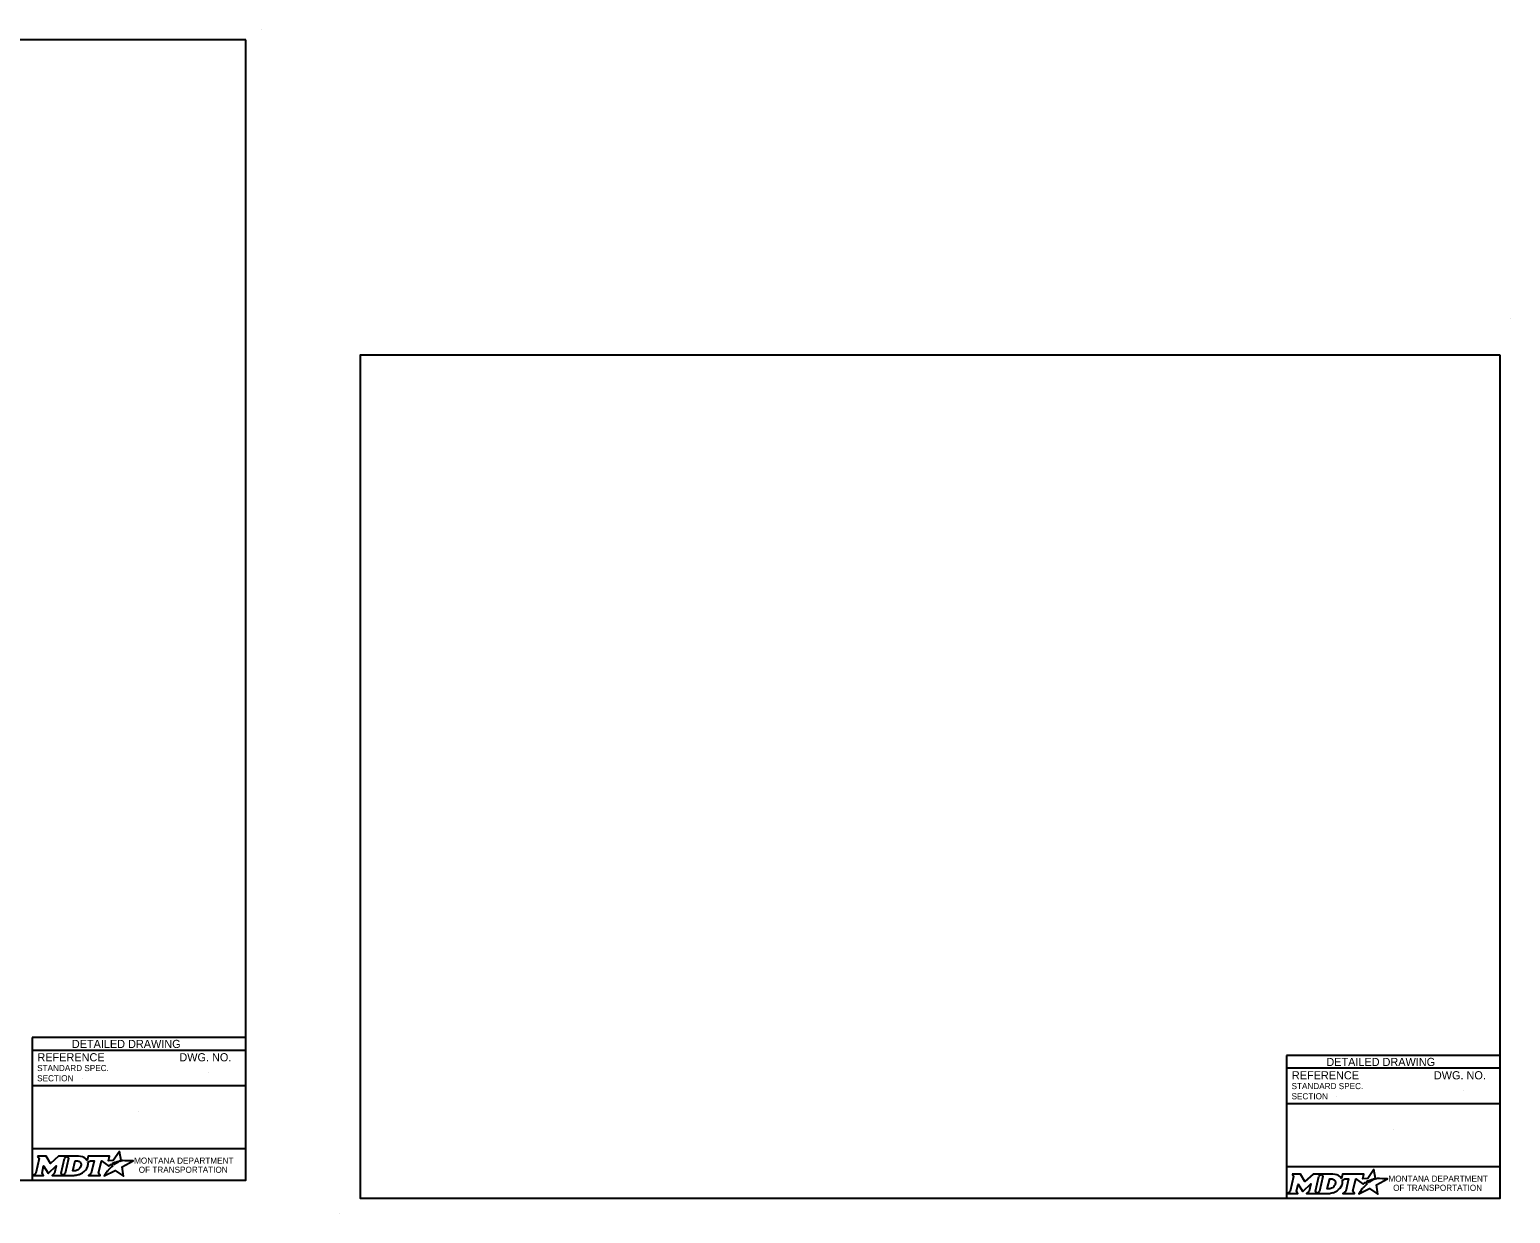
# Model space of a CAD drawing. Extents: x 49991.4 to 50021, y 49987.6 to 50011.4.
# Drawn here: x 50006.49 to 50021.04, y 49999.74 to 50011.36 of the extents above; entities that cross this region are included whole.
import ezdxf

# ---------------------------------------------------------------- set-up
doc = ezdxf.new("R2010")
doc.units = 0
for name, color, linetype in [('Default', 7, 'Continuous'), ('Level 1', 7, 'Continuous'), ('Level 2', 7, 'Continuous'), ('Level 4', 7, 'Continuous')]:
    doc.layers.add(name, color=color, linetype=linetype)

msp = doc.modelspace()

# ---------------------------------------------------------------- linework, layer by layer
at = {"layer": 'Default'}
for points in [[(50018.893, 50000.121), (50018.907, 50000.097), (50018.874, 49999.954), (50018.848, 49999.931), (50018.95, 49999.931), (50018.936, 49999.954), (50018.952, 50000.024), (50018.996, 49999.955), (50019.002, 49999.955), (50019.077, 50000.025), (50019.06, 49999.954), (50019.035, 49999.932), (50019.137, 49999.932), (50019.123, 49999.955), (50019.156, 50000.097)], [(50019.156, 50000.097), (50019.182, 50000.121), (50019.099, 50000.121), (50019.02, 50000.048), (50018.975, 50000.12), (50018.893, 50000.121)], [(50019.295, 50000.121), (50019.182, 50000.121), (50019.196, 50000.098), (50019.163, 49999.954), (50019.137, 49999.932), (50019.248, 49999.932)], [(50019.7, 50000.068), (50019.69, 50000.074), (50019.702, 50000.076), (50019.713, 50000.078), (50019.696, 50000.168), (50019.636, 50000.077), (50019.589, 50000.076), (50019.599, 50000.12), (50019.39, 50000.121), (50019.38, 50000.078), (50019.374, 50000.086)], [(50019.319, 50000.034), (50019.318, 50000.026), (50019.315, 50000.017), (50019.311, 50000.008), (50019.305, 50000.001), (50019.299, 49999.994), (50019.291, 49999.988), (50019.282, 49999.983), (50019.273, 49999.979), (50019.264, 49999.977), (50019.255, 49999.976), (50019.239, 49999.976), (50019.263, 50000.076), (50019.279, 50000.076), (50019.286, 50000.075), (50019.294, 50000.073), (50019.301, 50000.07), (50019.307, 50000.066), (50019.311, 50000.061), (50019.315, 50000.055), (50019.318, 50000.049), (50019.319, 50000.042), (50019.32, 50000.038), (50019.319, 50000.034)], [(50019.293, 49999.939), (50019.302, 49999.942), (50019.315, 49999.947), (50019.335, 49999.958)], [(50019.387, 50000.062), (50019.411, 50000.075), (50019.448, 50000.075), (50019.42, 49999.954), (50019.392, 49999.931), (50019.508, 49999.931), (50019.491, 49999.954), (50019.52, 50000.075), (50019.591, 50000.023), (50019.612, 50000.038), (50019.632, 50000.027)], [(50019.576, 49999.971), (50019.561, 49999.947), (50019.556, 49999.939), (50019.55, 49999.931), (50019.548, 49999.926), (50019.653, 49999.979), (50019.737, 49999.924), (50019.724, 50000.017), (50019.831, 50000.075), (50019.782, 50000.076), (50019.751, 50000.077), (50019.731, 50000.077), (50019.724, 50000.075), (50019.719, 50000.074), (50019.711, 50000.072), (50019.7, 50000.068)], [(50019.59, 49999.987), (50019.59, 49999.987)], [(50019.65, 50000.04), (50019.648, 50000.039), (50019.629, 50000.048), (50019.639, 50000.054), (50019.644, 50000.056), (50019.652, 50000.06), (50019.658, 50000.063), (50019.666, 50000.066), (50019.673, 50000.068), (50019.685, 50000.061), (50019.681, 50000.059), (50019.676, 50000.056), (50019.672, 50000.054), (50019.667, 50000.051), (50019.665, 50000.05), (50019.662, 50000.049), (50019.66, 50000.047), (50019.658, 50000.046), (50019.655, 50000.044), (50019.652, 50000.042), (50019.65, 50000.04)]]:
    msp.add_lwpolyline(points, dxfattribs=at)
for centre, radius, start, end in [((50019.274, 50000.059), 0.118, 300.9103, 339.1383), ((50019.319, 50000.042), 0.0709, 339.5329, 15.8582)]:
    msp.add_arc(centre, radius, start, end, dxfattribs=at)
for centre, major_axis, ratio, start_param, end_param in [((50019.293, 50000.073), (0.0834, -0.0037), 0.568097, 0.61298, 1.570796), ((50019.349, 50000.081), (0.0361, -0.0295), 0.469099, 1.225588, 1.570796), ((50019.583, 49999.979), (-0.00694, -0.00806), 0.008222, 0, 3.137361), ((50019.6, 49999.997), (-0.0098, -0.0102), 0.016458, 3.141593, 6.279097), ((50019.621, 50000.017), (-0.0112, -0.0097), 0.021651, 3.157348, 6.283185), ((50019.248, 50000.08), (0, 0.148), 0.987302, 3.139398, 3.456847)]:
    msp.add_ellipse(centre, major_axis=major_axis, ratio=ratio, start_param=start_param, end_param=end_param, dxfattribs=at)
at = {"layer": 'Level 1'}
for p, q in [((50008.765, 50011.363), (50008.765, 50011.363)), ((50021.038, 50008.524), (50021.038, 50008.524)), ((50009.537, 49999.736), (50009.537, 49999.736))]:
    msp.add_line(p, q, dxfattribs=at)
for points in [[(50008.615, 50011.263), (50000.336, 50011.263), (50000.336, 50000.062), (50008.615, 50000.062)], [(50020.938, 50008.165), (50009.737, 50008.165), (50009.737, 49999.886), (50020.938, 49999.886)]]:
    msp.add_lwpolyline(points, close=True, dxfattribs=at)
at = {"layer": 'Level 2'}
for p, q in [((50008.615, 50001.462), (50006.515, 50001.462)), ((50006.515, 50001.462), (50006.515, 50000.062)), ((50008.615, 50001.337), (50006.515, 50001.337)), ((50008.251, 50001.122), (50008.251, 50001.122)), ((50008.615, 50000.987), (50006.515, 50000.987)), ((50007.009, 50001.063), (50007.009, 50001.063)), ((50007.565, 50000.738), (50007.565, 50000.738)), ((50008.615, 50000.369), (50006.515, 50000.369))]:
    msp.add_line(p, q, dxfattribs=at)
for points in [[(50006.57, 50000.297), (50006.584, 50000.274), (50006.551, 50000.131), (50006.525, 50000.108), (50006.627, 50000.108), (50006.613, 50000.131), (50006.629, 50000.201), (50006.673, 50000.132), (50006.678, 50000.132), (50006.753, 50000.202), (50006.737, 50000.13), (50006.712, 50000.108), (50006.814, 50000.108), (50006.8, 50000.132), (50006.833, 50000.274)], [(50006.833, 50000.274), (50006.859, 50000.297), (50006.776, 50000.297), (50006.697, 50000.224), (50006.652, 50000.297), (50006.57, 50000.297)], [(50006.972, 50000.297), (50006.859, 50000.297), (50006.873, 50000.275), (50006.839, 50000.131), (50006.814, 50000.108), (50006.925, 50000.108)], [(50006.996, 50000.211), (50006.995, 50000.203), (50006.992, 50000.193), (50006.988, 50000.185), (50006.982, 50000.178), (50006.976, 50000.171), (50006.968, 50000.164), (50006.959, 50000.16), (50006.95, 50000.156), (50006.941, 50000.154), (50006.932, 50000.153), (50006.916, 50000.153), (50006.94, 50000.253), (50006.956, 50000.253), (50006.963, 50000.252), (50006.971, 50000.25), (50006.977, 50000.247), (50006.983, 50000.243), (50006.988, 50000.238), (50006.992, 50000.232), (50006.995, 50000.226), (50006.996, 50000.218), (50006.996, 50000.215), (50006.996, 50000.211)], [(50007.377, 50000.245), (50007.367, 50000.25), (50007.378, 50000.253), (50007.39, 50000.255), (50007.373, 50000.345), (50007.313, 50000.254), (50007.266, 50000.253), (50007.276, 50000.297), (50007.067, 50000.297), (50007.057, 50000.255), (50007.051, 50000.263)], [(50007.064, 50000.238), (50007.088, 50000.251), (50007.125, 50000.251), (50007.097, 50000.131), (50007.069, 50000.108), (50007.185, 50000.108), (50007.168, 50000.131), (50007.196, 50000.251), (50007.268, 50000.2), (50007.289, 50000.215), (50007.309, 50000.204)], [(50007.253, 50000.148), (50007.237, 50000.124), (50007.233, 50000.116), (50007.227, 50000.107), (50007.225, 50000.103), (50007.33, 50000.156), (50007.414, 50000.101), (50007.401, 50000.194), (50007.508, 50000.252), (50007.458, 50000.253), (50007.428, 50000.253), (50007.407, 50000.254), (50007.401, 50000.252), (50007.396, 50000.251), (50007.387, 50000.249), (50007.377, 50000.245)], [(50007.327, 50000.217), (50007.324, 50000.215), (50007.306, 50000.225), (50007.316, 50000.231), (50007.32, 50000.233), (50007.329, 50000.237), (50007.335, 50000.239), (50007.343, 50000.243), (50007.35, 50000.245), (50007.362, 50000.238), (50007.358, 50000.236), (50007.353, 50000.233), (50007.349, 50000.231), (50007.344, 50000.228), (50007.342, 50000.227), (50007.339, 50000.225), (50007.337, 50000.224), (50007.334, 50000.222), (50007.332, 50000.221), (50007.329, 50000.219), (50007.327, 50000.217)], [(50006.97, 50000.116), (50006.979, 50000.118), (50006.992, 50000.124), (50007.012, 50000.135)], [(50007.267, 50000.164), (50007.267, 50000.164)]]:
    msp.add_lwpolyline(points, dxfattribs=at)
for centre, radius, start, end in [((50006.995, 50000.219), 0.0709, 339.5329, 15.8582), ((50006.951, 50000.236), 0.118, 300.9103, 339.1383)]:
    msp.add_arc(centre, radius, start, end, dxfattribs=at)
for centre, major_axis, ratio, start_param, end_param in [((50006.97, 50000.25), (0.0834, -0.0037), 0.568097, 0.61298, 1.570796), ((50007.026, 50000.257), (0.0361, -0.0295), 0.469099, 1.225588, 1.570796), ((50006.925, 50000.257), (0, 0.148), 0.987302, 3.139398, 3.456847), ((50007.26, 50000.156), (-0.00694, -0.00806), 0.008222, 0, 3.137361), ((50007.276, 50000.174), (-0.0098, -0.0102), 0.016458, 3.141593, 6.279097), ((50007.297, 50000.194), (-0.0112, -0.0097), 0.021651, 3.157348, 6.283185)]:
    msp.add_ellipse(centre, major_axis=major_axis, ratio=ratio, start_param=start_param, end_param=end_param, dxfattribs=at)
at = {"layer": 'Level 4'}
for p, q in [((50020.938, 50001.286), (50018.838, 50001.286)), ((50018.838, 50001.286), (50018.838, 49999.886)), ((50020.938, 50001.161), (50018.838, 50001.161)), ((50019.332, 50000.886), (50019.332, 50000.886)), ((50020.574, 50000.946), (50020.574, 50000.946)), ((50020.938, 50000.811), (50018.838, 50000.811)), ((50019.888, 50000.562), (50019.888, 50000.562)), ((50020.938, 50000.193), (50018.838, 50000.193))]:
    msp.add_line(p, q, dxfattribs=at)

# ---------------------------------------------------------------- texts
at = {"layer": 'Default'}
for s, p in [('MONTANA DEPARTMENT', (50019.84, 50000.047)), ('OF TRANSPORTATION', (50019.886, 49999.957))]:
    msp.add_text(s, height=0.06, rotation=360, dxfattribs=at).set_placement(p)
at = {"layer": 'Level 2'}
for s, height, p in [('DETAILED DRAWING', 0.0799, (50006.906, 50001.36)), ('REFERENCE', 0.08, (50006.568, 50001.229)), ('DWG. NO.', 0.08, (50007.962, 50001.229)), ('STANDARD SPEC.', 0.06, (50006.565, 50001.133)), ('SECTION', 0.06, (50006.565, 50001.033))]:
    msp.add_text(s, height=height, dxfattribs=at).set_placement(p)
for s, p in [('MONTANA DEPARTMENT', (50007.517, 50000.224)), ('OF TRANSPORTATION', (50007.563, 50000.134))]:
    msp.add_text(s, height=0.06, rotation=360, dxfattribs=at).set_placement(p)
at = {"layer": 'Level 4'}
for s, height, p in [('DETAILED DRAWING', 0.0799, (50019.23, 50001.183)), ('REFERENCE', 0.08, (50018.891, 50001.052)), ('DWG. NO.', 0.08, (50020.286, 50001.052)), ('STANDARD SPEC.', 0.06, (50018.888, 50000.956)), ('SECTION', 0.06, (50018.888, 50000.856))]:
    msp.add_text(s, height=height, dxfattribs=at).set_placement(p)

doc.saveas('drawing.dxf')
